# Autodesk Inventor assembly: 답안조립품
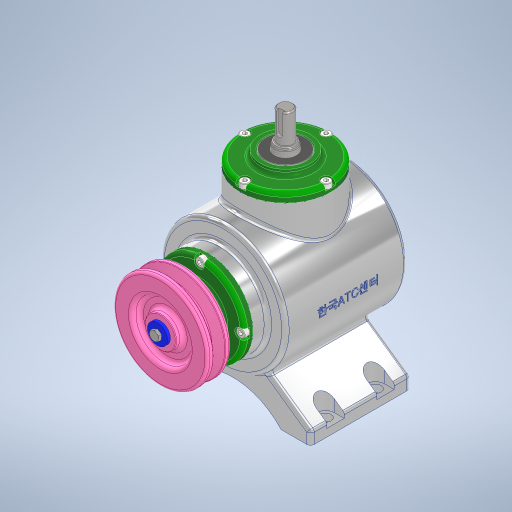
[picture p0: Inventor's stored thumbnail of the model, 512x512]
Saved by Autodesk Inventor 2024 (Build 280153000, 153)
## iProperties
Created: 2023-08
Part Number: 답안조립품
Document SubType Name: Assembly
Designer: Owner
Author: Owner
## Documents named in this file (17)
- C:\Users\Owner\Desktop\730813V1014\답안조립품.iam
- C:\Users\Owner\Desktop\730813V1014\본체.ipt
- C:\Users\Owner\Desktop\730813V1014\V-벨트풀리.ipt
- C:\Users\Owner\Desktop\730813V1014\메인 베벨기어.ipt
- C:\Users\Owner\Desktop\730813V1014\메인 축.ipt
- 메인 축.ipt
- C:\Users\Owner\Desktop\730813V1014\베어링 6203.ipt
- C:\Users\Owner\Desktop\730813V1014\볼트 M4 x 10.ipt
- C:\Users\Owner\Desktop\730813V1014\서브 베벨기어.ipt
- C:\Users\Owner\Desktop\730813V1014\서브 축.ipt
- 서브 축.ipt
- C:\Users\Owner\Desktop\730813V1014\오일실 17 x 32 x 8.ipt
- C:\Users\Owner\Desktop\730813V1014\와셔 4 x 16.ipt
- C:\Users\Owner\Desktop\730813V1014\육각볼트 M4 x 8.ipt
- C:\Users\Owner\Desktop\730813V1014\커버.ipt
- C:\Users\Owner\Desktop\730813V1014\키 4 x 4 x 14.ipt
- C:\Users\Owner\Desktop\730813V1014\키 5 x 5 x 14.ipt
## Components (1 placed, 1 different names)
1. V-벨트풀리:1 — 플러쉬:5, 각도:1
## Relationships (2: Flush 1, Angle 1)
- 플러쉬:5 [Flush]: V-벨트풀리:1
- 각도:1 [Angle]: V-벨트풀리:1
